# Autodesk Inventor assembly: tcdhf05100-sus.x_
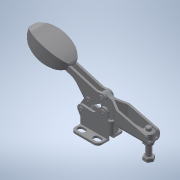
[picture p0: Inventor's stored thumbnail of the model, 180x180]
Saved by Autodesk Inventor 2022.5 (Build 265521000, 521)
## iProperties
Part Number: tcdhf05100-sus.x_
Material: 一般
Document SubType Name: Assembly
Designer: ImaoCorp
Sending System: SOLIDWORKS 2017-2017317
MC: AMD64
MC_MODEL: Intel64 Family 6 Model 60 Stepping 3, GenuineIntel
OS: Windows_NT
FRU: Parasolid Version 29.0, build 201,  4-17-2017
FORMAT: text
GUISE: transmit
KEY: tcdhf05100-sus
FILE: tcdhf05100-sus.x_t
DATE: Wed Sep 18 16:31:05 2019
Author: ImaoCorp
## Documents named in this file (8)
- X:\14_SW2022-Inv2022\00_全2023-1023新製品(TCC)まで\t\tcdhf05100-sus\TCDHF05100-SUS.iam
- X:\14_SW2022-Inv2022\00_全2023-1023新製品(TCC)まで\t\tcdhf05100-sus\tcdhf05100-sus_01.ipt
- X:\14_SW2022-Inv2022\00_全2023-1023新製品(TCC)まで\t\tcdhf05100-sus\tcdhf05100-sus_02.ipt
- X:\14_SW2022-Inv2022\00_全2023-1023新製品(TCC)まで\t\tcdhf05100-sus\tcdhf05100-sus_03.ipt
- X:\14_SW2022-Inv2022\00_全2023-1023新製品(TCC)まで\t\tcdhf05100-sus\tcdhf05100-sus_04.ipt
- X:\14_SW2022-Inv2022\00_全2023-1023新製品(TCC)まで\t\tcdhf05100-sus\tcdhf05100-sus_05.ipt
- X:\14_SW2022-Inv2022\00_全2023-1023新製品(TCC)まで\t\tcdhf05100-sus\tcdhf05100-sus_06.ipt
- X:\14_SW2022-Inv2022\00_全2023-1023新製品(TCC)まで\t\tcdhf05100-sus\tcdhf05100-sus_07.ipt
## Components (7 placed, 7 different names)
1. tcdhf05100-sus_01
2. tcdhf05100-sus_02
3. tcdhf05100-sus_03
4. tcdhf05100-sus_04
5. tcdhf05100-sus_05
6. tcdhf05100-sus_06
7. tcdhf05100-sus_07
